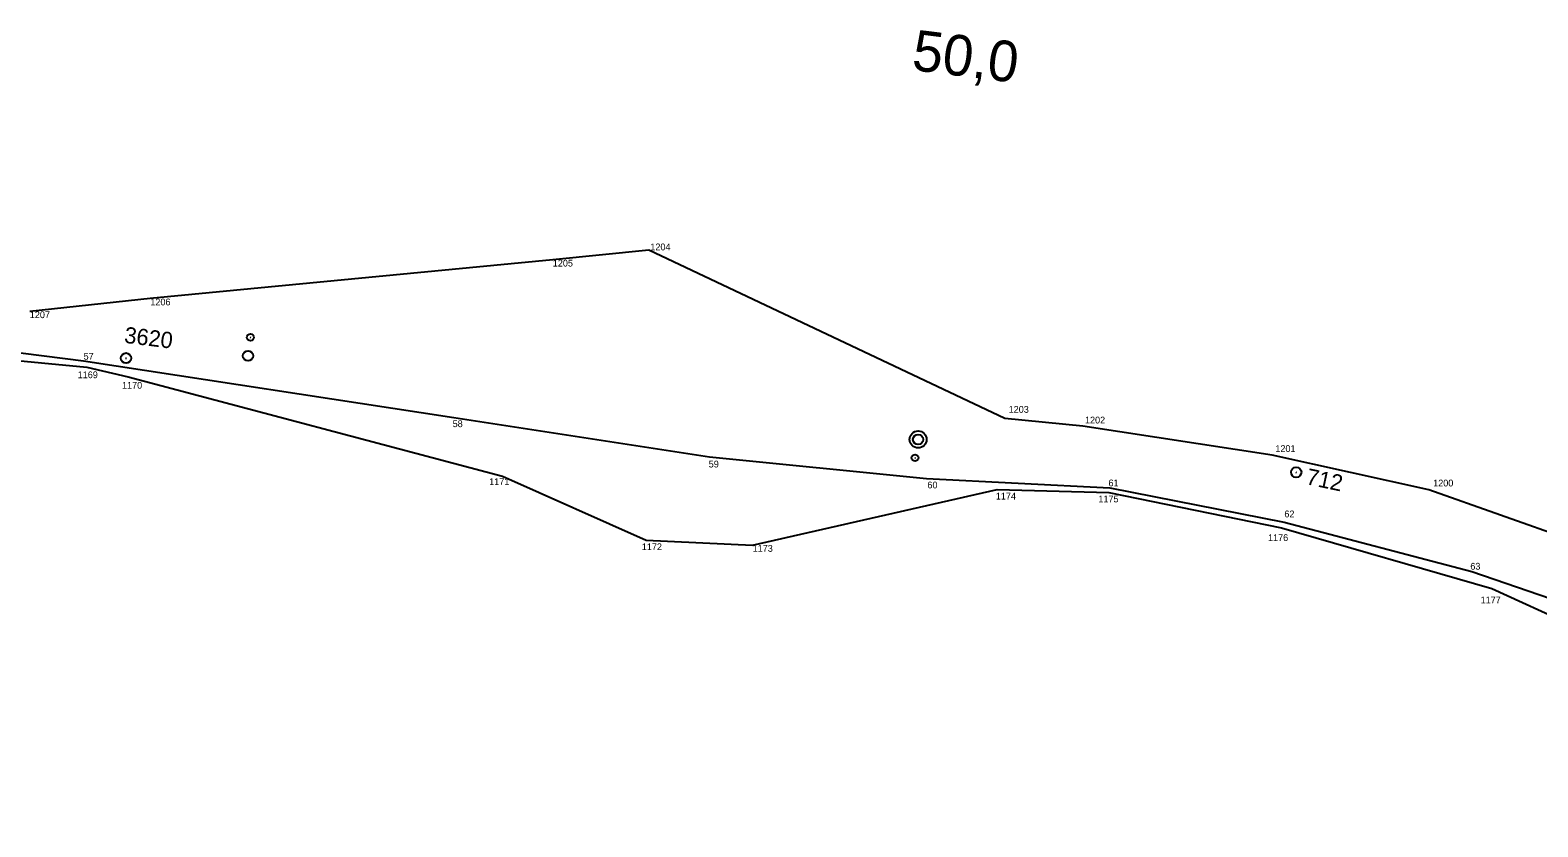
# Model space of a CAD drawing. Extents: x -678084 to -677195, y -1006706 to -1006195.
# Drawn here: x -677863.3 to -677640.8, y -1006433.1 to -1006315.4 of the extents above; entities that cross this region are included whole.
import ezdxf

# ---------------------------------------------------------------- set-up
doc = ezdxf.new("R2010")
doc.units = 0
for name, color, linetype in [('SSZT nové - lomové body', 7, 'Continuous'), ('SSZT_nové', 7, 'Continuous'), ('Stávající ŽBP', 7, 'Continuous'), ('SŽDC', 7, 'Continuous'), ('SŽDC - body', 7, 'Continuous'), ('Vrstva 7', 7, 'Continuous')]:
    doc.layers.add(name, color=color, linetype=linetype)

msp = doc.modelspace()

# ---------------------------------------------------------------- linework, layer by layer
at = {"layer": 'SSZT nové - lomové body'}
for p, q in [((-677855.43, -1006364.26), (-677855.43, -1006364.26)), ((-677800.81, -1006372.62), (-677800.81, -1006372.62)), ((-677763.07, -1006378.4), (-677763.07, -1006378.4)), ((-677730.99, -1006381.64), (-677730.99, -1006381.64)), ((-677703.96, -1006383), (-677703.96, -1006383)), ((-677678.22, -1006388.09), (-677678.22, -1006388.09)), ((-677650.5, -1006395.33), (-677650.5, -1006395.33))]:
    msp.add_line(p, q, dxfattribs=at)
at = {"layer": 'SSZT_nové'}
msp.add_lwpolyline([(-678046.18, -1006343.51), (-678039.76, -1006343.69), (-678028.1, -1006343.37), (-677988.11, -1006347.69), (-677946.88, -1006353.16), (-677896.95, -1006358.97), (-677855.43, -1006364.26), (-677800.81, -1006372.62), (-677763.07, -1006378.4), (-677730.99, -1006381.64), (-677703.96, -1006383), (-677678.22, -1006388.09), (-677650.5, -1006395.33), (-677540.71, -1006433.07)], dxfattribs=at)
at = {"layer": 'Stávající ŽBP'}
for p, q in [((-677849.23, -1006363.82), (-677849.13, -1006363.83)), ((-677676.48, -1006380.69), (-677676.38, -1006380.71))]:
    msp.add_line(p, q, dxfattribs=at)
for centre in [(-677849.18, -1006363.83), (-677676.43, -1006380.7)]:
    msp.add_circle(centre, 0.756, dxfattribs=at)
at = {"layer": 'SŽDC'}
for p, q in [((-677771.99, -1006347.9), (-677786.18, -1006349.31)), ((-677719.47, -1006372.74), (-677771.99, -1006347.9)), ((-677786.18, -1006349.31), (-677845.59, -1006355.04)), ((-677845.59, -1006355.04), (-677863.38, -1006356.93)), ((-677922.14, -1006358.97), (-677854.94, -1006365.15)), ((-677854.94, -1006365.15), (-677848.86, -1006366.62)), ((-677848.86, -1006366.62), (-677793.6, -1006381.25)), ((-677707.93, -1006373.88), (-677719.47, -1006372.74)), ((-677679.98, -1006378.16), (-677707.93, -1006373.88)), ((-677656.86, -1006383.31), (-677679.98, -1006378.16)), ((-677793.6, -1006381.25), (-677772.38, -1006390.75)), ((-677756.68, -1006391.44), (-677720.56, -1006383.26)), ((-677720.56, -1006383.26), (-677704.12, -1006383.69)), ((-677704.12, -1006383.69), (-677678.6, -1006388.92)), ((-677632.95, -1006391.74), (-677656.86, -1006383.31)), ((-677772.38, -1006390.75), (-677756.68, -1006391.44)), ((-677678.6, -1006388.92), (-677647.54, -1006397.88)), ((-677647.54, -1006397.88), (-677618.24, -1006411.32))]:
    msp.add_line(p, q, dxfattribs=at)
at = {"layer": 'SŽDC - body'}
for p, q in [((-677771.99, -1006347.9), (-677771.99, -1006347.9)), ((-677786.18, -1006349.31), (-677786.18, -1006349.31)), ((-677845.59, -1006355.04), (-677845.59, -1006355.04)), ((-677854.94, -1006365.15), (-677854.94, -1006365.15)), ((-677848.86, -1006366.62), (-677848.86, -1006366.62)), ((-677719.47, -1006372.74), (-677719.47, -1006372.74)), ((-677707.93, -1006373.88), (-677707.93, -1006373.88)), ((-677679.98, -1006378.16), (-677679.98, -1006378.16)), ((-677793.6, -1006381.25), (-677793.6, -1006381.25)), ((-677720.56, -1006383.26), (-677720.56, -1006383.26)), ((-677704.12, -1006383.69), (-677704.12, -1006383.69)), ((-677656.86, -1006383.31), (-677656.86, -1006383.31)), ((-677772.38, -1006390.75), (-677772.38, -1006390.75)), ((-677678.6, -1006388.92), (-677678.6, -1006388.92)), ((-677756.68, -1006391.44), (-677756.68, -1006391.44)), ((-677647.54, -1006397.88), (-677647.54, -1006397.88))]:
    msp.add_line(p, q, dxfattribs=at)
at = {"layer": 'Vrstva 7'}
for p, q in [((-677830.87, -1006360.76), (-677830.77, -1006360.78)), ((-677732.76, -1006378.56), (-677732.66, -1006378.57))]:
    msp.add_line(p, q, dxfattribs=at)
for centre, radius in [((-677830.82, -1006360.77), 0.5), ((-677831.17, -1006363.51), 0.75), ((-677732.26, -1006375.85), 1.25), ((-677732.26, -1006375.85), 0.752), ((-677732.71, -1006378.57), 0.5)]:
    msp.add_circle(centre, radius, dxfattribs=at)

# ---------------------------------------------------------------- texts
at = {"layer": 'SSZT nové - lomové body'}
for s, p in [('57', (-677855.44, -1006364.07)), ('58', (-677800.96, -1006374.03)), ('59', (-677763.16, -1006379.99)), ('60', (-677730.88, -1006383.08)), ('61', (-677704.15, -1006382.77)), ('62', (-677678.19, -1006387.35)), ('63', (-677650.74, -1006395.08))]:
    msp.add_text(s, height=1, dxfattribs=at).set_placement(p)
at = {"layer": 'Stávající ŽBP'}
for s, rotation, p in [('3620', 352.9578, (-677849.52, -1006361.57)), ('712', 348.1094, (-677675.1, -1006382.44))]:
    msp.add_text(s, height=2.4, rotation=rotation, dxfattribs=at).set_placement(p)
at = {"layer": 'SŽDC - body'}
for s, p in [('1204', (-677771.78, -1006347.91)), ('1205', (-677786.18, -1006350.31)), ('1206', (-677845.59, -1006356.04)), ('1207', (-677863.38, -1006357.93)), ('1169', (-677856.31, -1006366.8)), ('1170', (-677849.77, -1006368.35)), ('1203', (-677718.89, -1006371.91)), ('1202', (-677707.62, -1006373.49)), ('1201', (-677679.52, -1006377.7)), ('1171', (-677795.57, -1006382.58)), ('1200', (-677656.22, -1006382.79)), ('1174', (-677720.78, -1006384.72)), ('1175', (-677705.64, -1006385.14)), ('1176', (-677680.6, -1006390.85)), ('1172', (-677773.04, -1006392.2)), ('1173', (-677756.68, -1006392.44)), ('1177', (-677649.22, -1006400.05))]:
    msp.add_text(s, height=1, dxfattribs=at).set_placement(p)
at = {"layer": 'Vrstva 7'}
msp.add_text('50,0', height=6, rotation=352.9006, dxfattribs=at).set_placement((-677733.33, -1006321.26))

doc.saveas('drawing.dxf')
